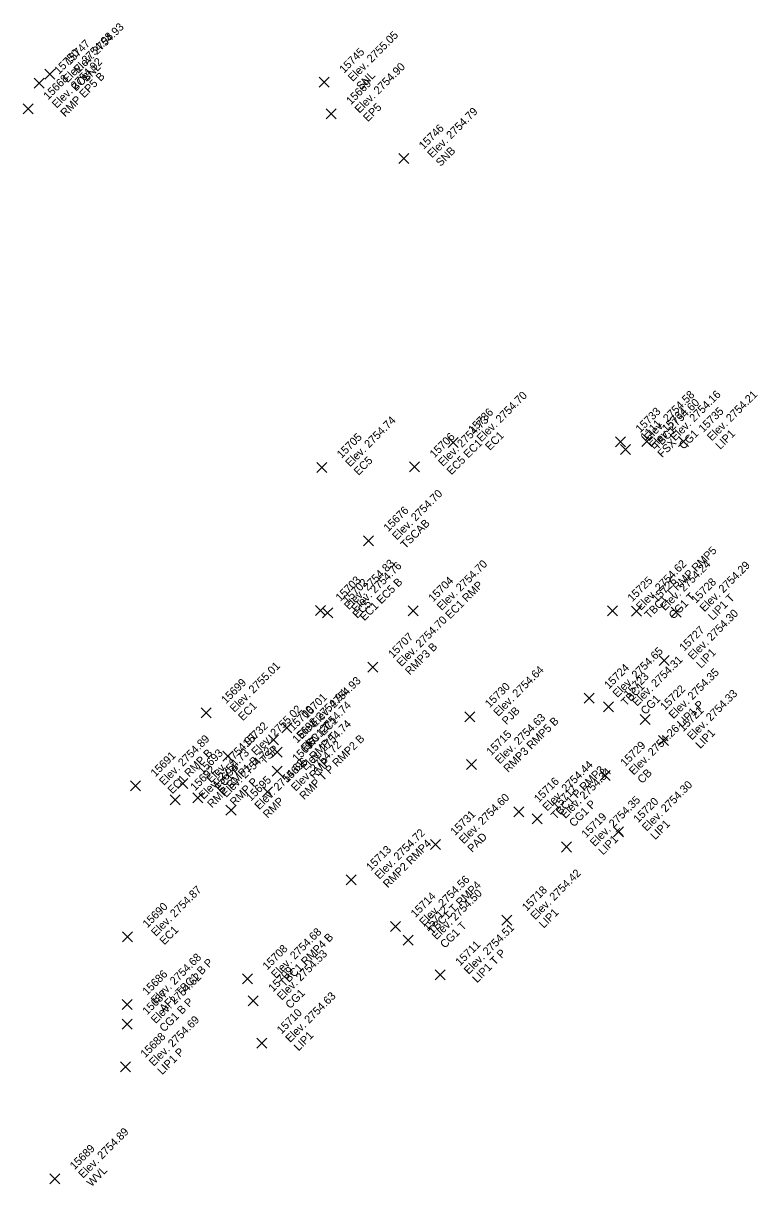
# Model space of a CAD drawing. Extents: x 2493999 to 2503109, y 700767 to 706646.
# Drawn here: x 2502242.58 to 2502264.59, y 703997.06 to 704031.91 of the extents above; entities that cross this region are included whole.
import ezdxf

# ---------------------------------------------------------------- set-up
doc = ezdxf.new("R2010")
doc.units = 0
doc.layers.add('ALG_CL_BLUE_Horiz', color=7, linetype='Continuous')
doc.layers.add('DES_SURFACE_Existing-Ground', color=7, linetype='Continuous')

msp = doc.modelspace()

# ---------------------------------------------------------------- linework, layer by layer
at = {"layer": 'ALG_CL_BLUE_Horiz'}
for points in [[(2502243.378, 704030.391), (2502243.228, 704030.541), (2502243.378, 704030.391), (2502243.228, 704030.241), (2502243.378, 704030.391), (2502243.528, 704030.241), (2502243.378, 704030.391), (2502243.528, 704030.541)], [(2502243.056, 704030.112), (2502242.906, 704030.262), (2502243.056, 704030.112), (2502242.906, 704029.962), (2502243.056, 704030.112), (2502243.206, 704029.962), (2502243.056, 704030.112), (2502243.206, 704030.262)], [(2502251.599, 704030.148), (2502251.449, 704030.298), (2502251.599, 704030.148), (2502251.449, 704029.998), (2502251.599, 704030.148), (2502251.749, 704029.998), (2502251.599, 704030.148), (2502251.749, 704030.298)], [(2502242.731, 704029.347), (2502242.581, 704029.497), (2502242.731, 704029.347), (2502242.581, 704029.197), (2502242.731, 704029.347), (2502242.881, 704029.197), (2502242.731, 704029.347), (2502242.881, 704029.497)], [(2502251.805, 704029.199), (2502251.655, 704029.349), (2502251.805, 704029.199), (2502251.655, 704029.049), (2502251.805, 704029.199), (2502251.955, 704029.049), (2502251.805, 704029.199), (2502251.955, 704029.349)], [(2502253.98, 704027.857), (2502253.83, 704028.007), (2502253.98, 704027.857), (2502253.83, 704027.707), (2502253.98, 704027.857), (2502254.13, 704027.707), (2502253.98, 704027.857), (2502254.13, 704028.007)], [(2502255.46, 704019.343), (2502255.31, 704019.493), (2502255.46, 704019.343), (2502255.31, 704019.193), (2502255.46, 704019.343), (2502255.61, 704019.193), (2502255.46, 704019.343), (2502255.61, 704019.493)], [(2502260.474, 704019.367), (2502260.324, 704019.517), (2502260.474, 704019.367), (2502260.324, 704019.217), (2502260.474, 704019.367), (2502260.624, 704019.217), (2502260.474, 704019.367), (2502260.624, 704019.517)], [(2502260.622, 704019.129), (2502260.472, 704019.279), (2502260.622, 704019.129), (2502260.472, 704018.979), (2502260.622, 704019.129), (2502260.772, 704018.979), (2502260.622, 704019.129), (2502260.772, 704019.279)], [(2502261.263, 704019.374), (2502261.113, 704019.524), (2502261.263, 704019.374), (2502261.113, 704019.224), (2502261.263, 704019.374), (2502261.413, 704019.224), (2502261.263, 704019.374), (2502261.413, 704019.524)], [(2502262.361, 704019.373), (2502262.211, 704019.523), (2502262.361, 704019.373), (2502262.211, 704019.223), (2502262.361, 704019.373), (2502262.511, 704019.223), (2502262.361, 704019.373), (2502262.511, 704019.523)], [(2502251.523, 704018.596), (2502251.373, 704018.746), (2502251.523, 704018.596), (2502251.373, 704018.446), (2502251.523, 704018.596), (2502251.673, 704018.446), (2502251.523, 704018.596), (2502251.673, 704018.746)], [(2502254.306, 704018.609), (2502254.156, 704018.759), (2502254.306, 704018.609), (2502254.156, 704018.459), (2502254.306, 704018.609), (2502254.456, 704018.459), (2502254.306, 704018.609), (2502254.456, 704018.759)], [(2502252.923, 704016.399), (2502252.773, 704016.549), (2502252.923, 704016.399), (2502252.773, 704016.249), (2502252.923, 704016.399), (2502253.073, 704016.249), (2502252.923, 704016.399), (2502253.073, 704016.549)], [(2502251.487, 704014.308), (2502251.337, 704014.458), (2502251.487, 704014.308), (2502251.337, 704014.158), (2502251.487, 704014.308), (2502251.637, 704014.158), (2502251.487, 704014.308), (2502251.637, 704014.458)], [(2502254.267, 704014.291), (2502254.117, 704014.441), (2502254.267, 704014.291), (2502254.117, 704014.141), (2502254.267, 704014.291), (2502254.417, 704014.141), (2502254.267, 704014.291), (2502254.417, 704014.441)], [(2502260.233, 704014.294), (2502260.083, 704014.444), (2502260.233, 704014.294), (2502260.083, 704014.144), (2502260.233, 704014.294), (2502260.383, 704014.144), (2502260.233, 704014.294), (2502260.383, 704014.444)], [(2502260.958, 704014.283), (2502260.808, 704014.433), (2502260.958, 704014.283), (2502260.808, 704014.133), (2502260.958, 704014.283), (2502261.108, 704014.133), (2502260.958, 704014.283), (2502261.108, 704014.433)], [(2502262.138, 704014.251), (2502261.988, 704014.401), (2502262.138, 704014.251), (2502261.988, 704014.101), (2502262.138, 704014.251), (2502262.288, 704014.101), (2502262.138, 704014.251), (2502262.288, 704014.401)], [(2502251.701, 704014.234), (2502251.551, 704014.384), (2502251.701, 704014.234), (2502251.551, 704014.084), (2502251.701, 704014.234), (2502251.851, 704014.084), (2502251.701, 704014.234), (2502251.851, 704014.384)], [(2502253.059, 704012.61), (2502252.909, 704012.76), (2502253.059, 704012.61), (2502252.909, 704012.46), (2502253.059, 704012.61), (2502253.209, 704012.46), (2502253.059, 704012.61), (2502253.209, 704012.76)], [(2502261.786, 704012.81), (2502261.636, 704012.96), (2502261.786, 704012.81), (2502261.636, 704012.66), (2502261.786, 704012.81), (2502261.936, 704012.66), (2502261.786, 704012.81), (2502261.936, 704012.96)], [(2502259.532, 704011.679), (2502259.382, 704011.829), (2502259.532, 704011.679), (2502259.382, 704011.529), (2502259.532, 704011.679), (2502259.682, 704011.529), (2502259.532, 704011.679), (2502259.682, 704011.829)], [(2502248.059, 704011.236), (2502247.909, 704011.386), (2502248.059, 704011.236), (2502247.909, 704011.086), (2502248.059, 704011.236), (2502248.209, 704011.086), (2502248.059, 704011.236), (2502248.209, 704011.386)], [(2502255.96, 704011.117), (2502255.81, 704011.267), (2502255.96, 704011.117), (2502255.81, 704010.967), (2502255.96, 704011.117), (2502256.11, 704010.967), (2502255.96, 704011.117), (2502256.11, 704011.267)], [(2502260.118, 704011.42), (2502259.968, 704011.57), (2502260.118, 704011.42), (2502259.968, 704011.27), (2502260.118, 704011.42), (2502260.268, 704011.27), (2502260.118, 704011.42), (2502260.268, 704011.57)], [(2502250.48, 704010.792), (2502250.33, 704010.942), (2502250.48, 704010.792), (2502250.33, 704010.642), (2502250.48, 704010.792), (2502250.63, 704010.642), (2502250.48, 704010.792), (2502250.63, 704010.942)], [(2502261.212, 704011.041), (2502261.062, 704011.191), (2502261.212, 704011.041), (2502261.062, 704010.891), (2502261.212, 704011.041), (2502261.362, 704010.891), (2502261.212, 704011.041), (2502261.362, 704011.191)], [(2502250.076, 704010.427), (2502249.926, 704010.577), (2502250.076, 704010.427), (2502249.926, 704010.277), (2502250.076, 704010.427), (2502250.226, 704010.277), (2502250.076, 704010.427), (2502250.226, 704010.577)], [(2502261.76, 704010.404), (2502261.61, 704010.554), (2502261.76, 704010.404), (2502261.61, 704010.254), (2502261.76, 704010.404), (2502261.91, 704010.254), (2502261.76, 704010.404), (2502261.91, 704010.554)], [(2502248.707, 704009.936), (2502248.557, 704010.086), (2502248.707, 704009.936), (2502248.557, 704009.786), (2502248.707, 704009.936), (2502248.857, 704009.786), (2502248.707, 704009.936), (2502248.857, 704010.086)], [(2502250.189, 704010.056), (2502250.039, 704010.206), (2502250.189, 704010.056), (2502250.039, 704009.906), (2502250.189, 704010.056), (2502250.339, 704009.906), (2502250.189, 704010.056), (2502250.339, 704010.206)], [(2502250.19, 704009.493), (2502250.04, 704009.643), (2502250.19, 704009.493), (2502250.04, 704009.343), (2502250.19, 704009.493), (2502250.34, 704009.343), (2502250.19, 704009.493), (2502250.34, 704009.643)], [(2502256.007, 704009.687), (2502255.857, 704009.837), (2502256.007, 704009.687), (2502255.857, 704009.537), (2502256.007, 704009.687), (2502256.157, 704009.537), (2502256.007, 704009.687), (2502256.157, 704009.837)], [(2502245.944, 704009.045), (2502245.794, 704009.195), (2502245.944, 704009.045), (2502245.794, 704008.895), (2502245.944, 704009.045), (2502246.094, 704008.895), (2502245.944, 704009.045), (2502246.094, 704009.195)], [(2502247.36, 704009.122), (2502247.21, 704009.272), (2502247.36, 704009.122), (2502247.21, 704008.972), (2502247.36, 704009.122), (2502247.51, 704008.972), (2502247.36, 704009.122), (2502247.51, 704009.272)], [(2502260.02, 704009.356), (2502259.87, 704009.506), (2502260.02, 704009.356), (2502259.87, 704009.206), (2502260.02, 704009.356), (2502260.17, 704009.206), (2502260.02, 704009.356), (2502260.17, 704009.506)], [(2502247.811, 704008.686), (2502247.661, 704008.836), (2502247.811, 704008.686), (2502247.661, 704008.536), (2502247.811, 704008.686), (2502247.961, 704008.536), (2502247.811, 704008.686), (2502247.961, 704008.836)], [(2502249.895, 704008.869), (2502249.745, 704009.019), (2502249.895, 704008.869), (2502249.745, 704008.719), (2502249.895, 704008.869), (2502250.045, 704008.719), (2502249.895, 704008.869), (2502250.045, 704009.019)], [(2502247.133, 704008.629), (2502246.983, 704008.779), (2502247.133, 704008.629), (2502246.983, 704008.479), (2502247.133, 704008.629), (2502247.283, 704008.479), (2502247.133, 704008.629), (2502247.283, 704008.779)], [(2502248.805, 704008.315), (2502248.655, 704008.465), (2502248.805, 704008.315), (2502248.655, 704008.165), (2502248.805, 704008.315), (2502248.955, 704008.165), (2502248.805, 704008.315), (2502248.955, 704008.465)], [(2502257.431, 704008.273), (2502257.281, 704008.423), (2502257.431, 704008.273), (2502257.281, 704008.123), (2502257.431, 704008.273), (2502257.581, 704008.123), (2502257.431, 704008.273), (2502257.581, 704008.423)], [(2502257.974, 704008.055), (2502257.824, 704008.205), (2502257.974, 704008.055), (2502257.824, 704007.905), (2502257.974, 704008.055), (2502258.124, 704007.905), (2502257.974, 704008.055), (2502258.124, 704008.205)], [(2502260.41, 704007.67), (2502260.26, 704007.82), (2502260.41, 704007.67), (2502260.26, 704007.52), (2502260.41, 704007.67), (2502260.56, 704007.52), (2502260.41, 704007.67), (2502260.56, 704007.82)], [(2502254.928, 704007.289), (2502254.778, 704007.439), (2502254.928, 704007.289), (2502254.778, 704007.139), (2502254.928, 704007.289), (2502255.078, 704007.139), (2502254.928, 704007.289), (2502255.078, 704007.439)], [(2502258.852, 704007.215), (2502258.702, 704007.365), (2502258.852, 704007.215), (2502258.702, 704007.065), (2502258.852, 704007.215), (2502259.002, 704007.065), (2502258.852, 704007.215), (2502259.002, 704007.365)], [(2502252.401, 704006.228), (2502252.251, 704006.378), (2502252.401, 704006.228), (2502252.251, 704006.078), (2502252.401, 704006.228), (2502252.551, 704006.078), (2502252.401, 704006.228), (2502252.551, 704006.378)], [(2502257.071, 704005.019), (2502256.921, 704005.169), (2502257.071, 704005.019), (2502256.921, 704004.869), (2502257.071, 704005.019), (2502257.221, 704004.869), (2502257.071, 704005.019), (2502257.221, 704005.169)], [(2502245.704, 704004.521), (2502245.554, 704004.671), (2502245.704, 704004.521), (2502245.554, 704004.371), (2502245.704, 704004.521), (2502245.854, 704004.371), (2502245.704, 704004.521), (2502245.854, 704004.671)], [(2502253.737, 704004.831), (2502253.587, 704004.981), (2502253.737, 704004.831), (2502253.587, 704004.681), (2502253.737, 704004.831), (2502253.887, 704004.681), (2502253.737, 704004.831), (2502253.887, 704004.981)], [(2502254.11, 704004.418), (2502253.96, 704004.568), (2502254.11, 704004.418), (2502253.96, 704004.268), (2502254.11, 704004.418), (2502254.26, 704004.268), (2502254.11, 704004.418), (2502254.26, 704004.568)], [(2502249.299, 704003.258), (2502249.149, 704003.408), (2502249.299, 704003.258), (2502249.149, 704003.108), (2502249.299, 704003.258), (2502249.449, 704003.108), (2502249.299, 704003.258), (2502249.449, 704003.408)], [(2502255.074, 704003.382), (2502254.924, 704003.532), (2502255.074, 704003.382), (2502254.924, 704003.232), (2502255.074, 704003.382), (2502255.224, 704003.232), (2502255.074, 704003.382), (2502255.224, 704003.532)], [(2502245.698, 704002.497), (2502245.548, 704002.647), (2502245.698, 704002.497), (2502245.548, 704002.347), (2502245.698, 704002.497), (2502245.848, 704002.347), (2502245.698, 704002.497), (2502245.848, 704002.647)], [(2502249.473, 704002.603), (2502249.323, 704002.753), (2502249.473, 704002.603), (2502249.323, 704002.453), (2502249.473, 704002.603), (2502249.623, 704002.453), (2502249.473, 704002.603), (2502249.623, 704002.753)], [(2502245.698, 704001.907), (2502245.548, 704002.057), (2502245.698, 704001.907), (2502245.548, 704001.757), (2502245.698, 704001.907), (2502245.848, 704001.757), (2502245.698, 704001.907), (2502245.848, 704002.057)], [(2502249.726, 704001.338), (2502249.576, 704001.488), (2502249.726, 704001.338), (2502249.576, 704001.188), (2502249.726, 704001.338), (2502249.876, 704001.188), (2502249.726, 704001.338), (2502249.876, 704001.488)], [(2502245.64, 704000.624), (2502245.49, 704000.774), (2502245.64, 704000.624), (2502245.49, 704000.474), (2502245.64, 704000.624), (2502245.79, 704000.474), (2502245.64, 704000.624), (2502245.79, 704000.774)], [(2502243.523, 703997.266), (2502243.373, 703997.416), (2502243.523, 703997.266), (2502243.373, 703997.116), (2502243.523, 703997.266), (2502243.673, 703997.116), (2502243.523, 703997.266), (2502243.673, 703997.416)]]:
    msp.add_lwpolyline(points, dxfattribs=at)

# ---------------------------------------------------------------- texts
at = {"layer": 'DES_SURFACE_Existing-Ground'}
for s, p in [('Elev. 2754.93', (2502244.227, 704030.391)), ('Elev. 2754.98', (2502243.905, 704030.112)), ('Elev. 2755.05', (2502252.448, 704030.148)), ('15750', (2502243.65, 704030.367)), ('15747', (2502243.972, 704030.646)), ('15745', (2502252.193, 704030.403)), ('Elev. 2754.92', (2502243.58, 704029.347)), ('RMP EP5 B', (2502243.834, 704029.092)), ('SNL', (2502244.481, 704030.136)), ('Elev. 2754.90', (2502252.654, 704029.199)), ('15668', (2502243.325, 704029.602)), ('BOL', (2502244.159, 704029.857)), ('15669', (2502252.399, 704029.454)), ('SNL', (2502252.702, 704029.893)), ('EP5', (2502252.908, 704028.944)), ('Elev. 2754.79', (2502254.829, 704027.857)), ('15746', (2502254.574, 704028.112)), ('SNB', (2502255.083, 704027.602)), ('Elev. 2754.70', (2502256.309, 704019.343)), ('Elev. 2754.58', (2502261.323, 704019.367)), ('Elev. 2754.16', (2502262.112, 704019.374)), ('Elev. 2754.21', (2502263.21, 704019.373)), ('15736', (2502256.054, 704019.598)), ('15733', (2502261.068, 704019.622)), ('Elev. 2754.60', (2502261.471, 704019.129)), ('15734', (2502261.857, 704019.629)), ('15735', (2502262.955, 704019.628)), ('Elev. 2754.74', (2502252.372, 704018.596)), ('Elev. 2754.73', (2502255.155, 704018.609)), ('1111', (2502261.216, 704019.384)), ('15705', (2502252.117, 704018.851)), ('15706', (2502254.9, 704018.864)), ('EC1', (2502256.563, 704019.088)), ('TBC1', (2502261.577, 704019.112)), ('CG1', (2502262.366, 704019.119)), ('LIP1', (2502263.464, 704019.118)), ('EC5 EC1', (2502255.409, 704018.354)), ('FSX', (2502261.725, 704018.874)), ('EC5', (2502252.626, 704018.341)), ('Elev. 2754.70', (2502253.772, 704016.399)), ('15676', (2502253.517, 704016.654)), ('TSCAB', (2502254.026, 704016.144)), ('TBC1 T RMP RMP5', (2502261.336, 704014.039)), ('Elev. 2754.83', (2502252.336, 704014.308)), ('Elev. 2754.70', (2502255.116, 704014.291)), ('Elev. 2754.62', (2502261.082, 704014.294)), ('Elev. 2754.24', (2502261.807, 704014.283)), ('Elev. 2754.76', (2502252.55, 704014.234)), ('Elev. 2754.29', (2502262.987, 704014.251)), ('15703', (2502252.081, 704014.563)), ('15702', (2502252.295, 704014.489)), ('EC1 EC5 B', (2502252.804, 704013.979)), ('15704', (2502254.861, 704014.546)), ('EC1 RMP', (2502255.37, 704014.036)), ('15725', (2502260.827, 704014.549)), ('15726', (2502261.552, 704014.538)), ('15728', (2502262.732, 704014.506)), ('CG1 T', (2502262.061, 704014.028)), ('LIP1 T', (2502263.241, 704013.996)), ('EC5', (2502252.59, 704014.053)), ('Elev. 2754.70', (2502253.908, 704012.61)), ('Elev. 2754.30', (2502262.635, 704012.81)), ('15727', (2502262.38, 704013.065)), ('15707', (2502253.653, 704012.865)), ('RMP3 B', (2502254.162, 704012.355)), ('Elev. 2754.65', (2502260.381, 704011.679)), ('LIP1', (2502262.889, 704012.555)), ('Elev. 2755.01', (2502248.908, 704011.236)), ('15724', (2502260.126, 704011.934)), ('Elev. 2754.31', (2502260.967, 704011.42)), ('Elev. 2754.93', (2502251.329, 704010.792)), ('Elev. 2754.64', (2502256.809, 704011.117)), ('15723', (2502260.712, 704011.675)), ('Elev. 2754.35', (2502262.061, 704011.041)), ('15699', (2502248.653, 704011.491)), ('15730', (2502256.554, 704011.372)), ('TBC1', (2502260.635, 704011.424)), ('15722', (2502261.806, 704011.296)), ('Elev. 2754.94', (2502250.925, 704010.427)), ('15701', (2502251.074, 704011.047)), ('CG1', (2502261.221, 704011.165)), ('Elev. 2754.33', (2502262.609, 704010.404)), ('EC1', (2502249.162, 704010.981)), ('Elev. 2755.02', (2502249.556, 704009.936)), ('15700', (2502250.67, 704010.682)), ('Elev. 2754.74', (2502251.038, 704010.056)), ('PJB', (2502257.063, 704010.862)), ('LIP1 P', (2502262.315, 704010.786)), ('15721', (2502262.354, 704010.659)), ('15732', (2502249.301, 704010.191)), ('15698', (2502250.783, 704010.311)), ('Elev. 2754.74', (2502251.039, 704009.493)), ('EC1 T', (2502251.179, 704010.172)), ('EC1', (2502251.583, 704010.537)), ('Elev. 2754.63', (2502256.856, 704009.687)), ('RMP3 RMP5 B', (2502257.11, 704009.432)), ('Elev. 2754.89', (2502246.793, 704009.045)), ('Elev. 2754.91', (2502248.209, 704009.122)), ('RMP T P RMP2 B', (2502250.998, 704008.614)), ('RMP T', (2502251.292, 704009.801)), ('15715', (2502256.601, 704009.942)), ('Elev. 2754.26', (2502260.869, 704009.356)), ('LIP1', (2502262.863, 704010.149)), ('TSP', (2502249.81, 704009.681)), ('Elev. 2754.72', (2502250.744, 704008.869)), ('15697', (2502250.784, 704009.748)), ('15729', (2502260.614, 704009.611)), ('15691', (2502246.538, 704009.3)), ('EC1 RMP B', (2502247.047, 704008.79)), ('Elev. 2754.73', (2502247.982, 704008.629)), ('15693', (2502247.954, 704009.377)), ('RMP RMP1 B', (2502248.236, 704008.374)), ('Elev. 2754.72', (2502248.66, 704008.686)), ('15696', (2502250.489, 704009.124)), ('RMP', (2502251.293, 704009.238)), ('15692', (2502247.727, 704008.884)), ('15694', (2502248.405, 704008.941)), ('EC1 P', (2502248.463, 704008.867)), ('Elev. 2754.62', (2502249.654, 704008.315)), ('Elev. 2754.44', (2502258.28, 704008.273)), ('TBC1 P RMP3', (2502258.534, 704008.018)), ('Elev. 2754.34', (2502258.823, 704008.055)), ('CB', (2502261.123, 704009.101)), ('RMP P', (2502248.914, 704008.431)), ('15695', (2502249.399, 704008.57)), ('15716', (2502258.025, 704008.528)), ('Elev. 2754.30', (2502261.259, 704007.67)), ('15717', (2502258.568, 704008.31)), ('RMP', (2502249.908, 704008.06)), ('Elev. 2754.60', (2502255.777, 704007.289)), ('CG1 P', (2502259.077, 704007.8)), ('Elev. 2754.35', (2502259.701, 704007.215)), ('15720', (2502261.004, 704007.925)), ('15731', (2502255.522, 704007.544)), ('15719', (2502259.446, 704007.47)), ('LIP1 T', (2502259.955, 704006.96)), ('LIP1', (2502261.513, 704007.415)), ('Elev. 2754.72', (2502253.25, 704006.228)), ('RMP2 RMP4', (2502253.504, 704005.973)), ('PAD', (2502256.031, 704007.034)), ('15713', (2502252.995, 704006.483)), ('Elev. 2754.42', (2502257.92, 704005.019)), ('Elev. 2754.87', (2502246.553, 704004.521)), ('Elev. 2754.56', (2502254.586, 704004.831)), ('TBC1 T RMP4', (2502254.84, 704004.576)), ('15718', (2502257.665, 704005.274)), ('15714', (2502254.331, 704005.086)), ('Elev. 2754.50', (2502254.959, 704004.418)), ('15690', (2502246.298, 704004.776)), ('15712', (2502254.704, 704004.673)), ('LIP1', (2502258.174, 704004.764)), ('CG1 T', (2502255.213, 704004.163)), ('EC1', (2502246.807, 704004.266)), ('Elev. 2754.68', (2502250.148, 704003.258)), ('TBC1 RMP4 B', (2502250.402, 704003.003)), ('Elev. 2754.51', (2502255.923, 704003.382)), ('15711', (2502255.668, 704003.637)), ('Elev. 2754.68', (2502246.547, 704002.497)), ('15708', (2502249.893, 704003.513)), ('Elev. 2754.53', (2502250.322, 704002.603)), ('LIP1 T P', (2502256.177, 704003.127)), ('AFL TBC1 B P', (2502246.801, 704002.242)), ('15709', (2502250.067, 704002.858)), ('15686', (2502246.292, 704002.752)), ('Elev. 2754.62', (2502246.547, 704001.907)), ('15687', (2502246.292, 704002.162)), ('CG1', (2502250.576, 704002.348)), ('CG1 B P', (2502246.801, 704001.652)), ('Elev. 2754.63', (2502250.575, 704001.338)), ('15710', (2502250.32, 704001.593)), ('Elev. 2754.69', (2502246.489, 704000.624)), ('15688', (2502246.234, 704000.879)), ('LIP1', (2502250.829, 704001.083)), ('LIP1 P', (2502246.743, 704000.369)), ('Elev. 2754.89', (2502244.372, 703997.266)), ('15689', (2502244.117, 703997.521)), ('WVL', (2502244.626, 703997.011))]:
    msp.add_text(s, height=0.24, rotation=45, dxfattribs=at).set_placement(p)

doc.saveas('drawing.dxf')
